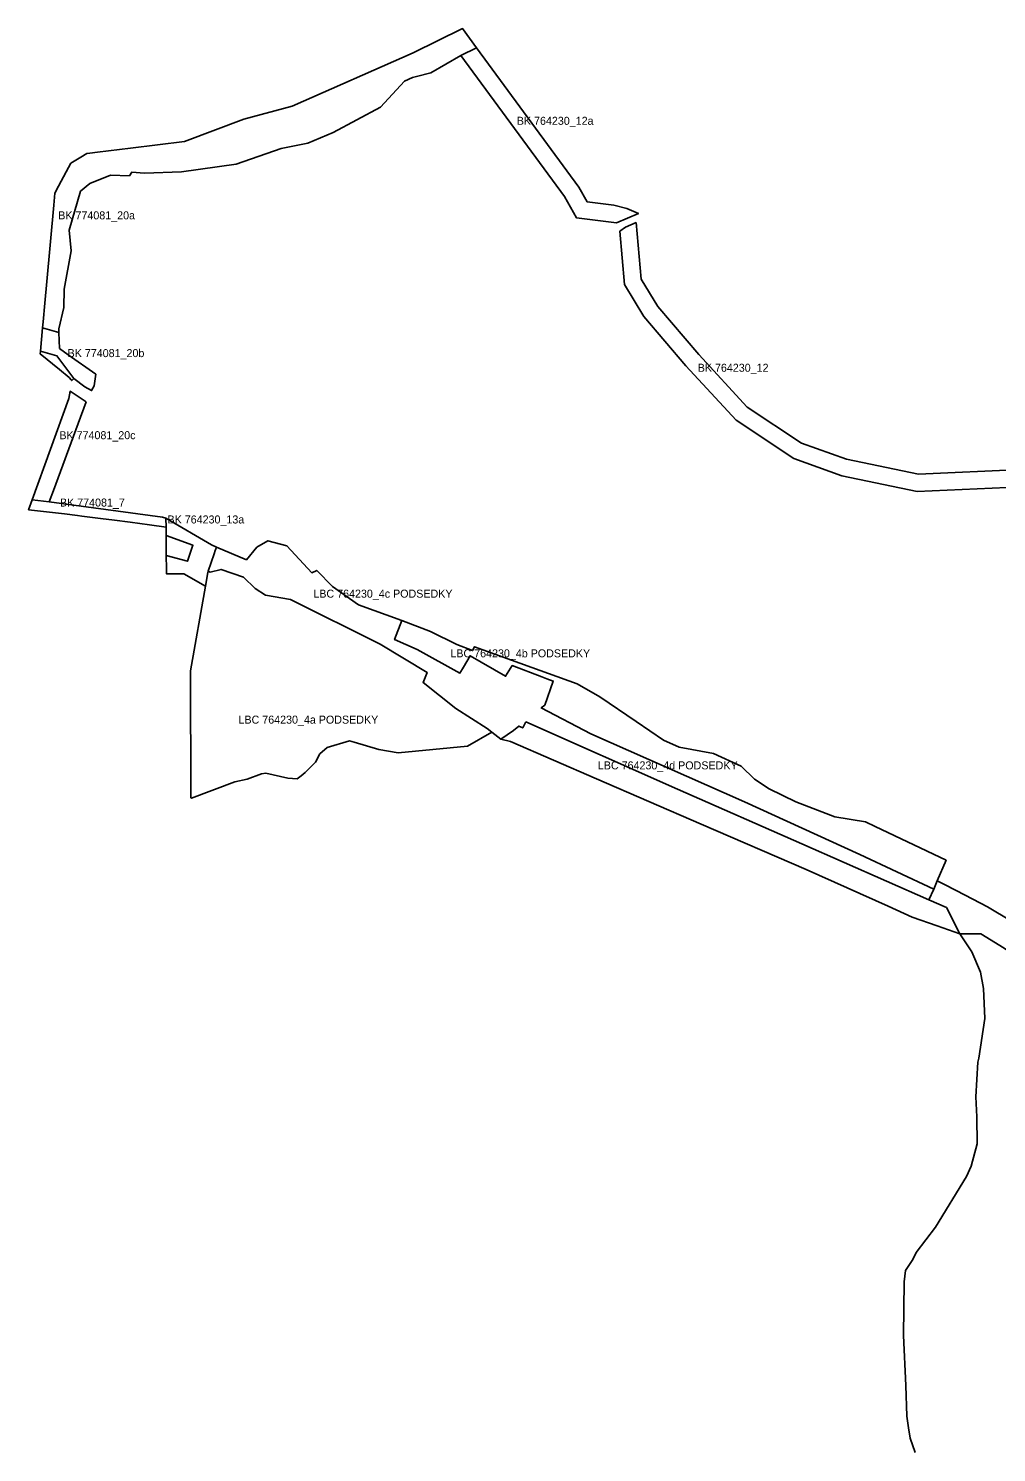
# Model space of a CAD drawing. Extents: x -521616 to -516782, y -1190061 to -1184927.
# Drawn here: x -520810 to -519963, y -1187423 to -1186178 of the extents above; entities that cross this region are included whole.
import ezdxf

# ---------------------------------------------------------------- set-up
doc = ezdxf.new("R2010")
doc.units = 0
for name, color, linetype in [('i_prvek_l_s', 7, 'Continuous'), ('LBC_n', 7, 'Continuous'), ('LBC_s', 7, 'Continuous'), ('LBK_n', 7, 'Continuous'), ('LBK_s', 7, 'Continuous')]:
    doc.layers.add(name, color=color, linetype=linetype)

msp = doc.modelspace()

# ---------------------------------------------------------------- linework, layer by layer
at = {"layer": 'i_prvek_l_s'}
msp.add_lwpolyline([(-520033.7, -1187423.2), (-520038, -1187410.6), (-520039.7, -1187401.5), (-520041.1, -1187391.5), (-520042, -1187364.5), (-520044, -1187320.9), (-520043.3, -1187273.9), (-520042.2, -1187263.9), (-520035.7, -1187254.5), (-520032.9, -1187248.3), (-520016.1, -1187226.1), (-519988.8, -1187181.8), (-519984.8, -1187172.8), (-519979.5, -1187153.1), (-519979.7, -1187129.6), (-519980.7, -1187112.2), (-519979, -1187081.9), (-519978.2, -1187078.4), (-519972.8, -1187043.7), (-519974, -1187017.4), (-519976.6, -1187003), (-519984.1, -1186985.3), (-519994.8, -1186969.5)], dxfattribs=at)
at = {"layer": 'LBC_n'}
msp.add_line((-520652.2, -1186652.3), (-520652.2, -1186652.3), dxfattribs=at)
for points in [[(-520667.4, -1186850.6), (-520667.8, -1186739.5), (-520654.8, -1186665.4), (-520652.7, -1186653.6), (-520652.2, -1186652.3), (-520650.6, -1186653.1), (-520641, -1186650.8), (-520621.4, -1186657.5), (-520611.2, -1186667.5), (-520602.1, -1186673.3), (-520580.3, -1186677), (-520501.9, -1186716.2), (-520460.6, -1186741.1), (-520464.3, -1186749.8), (-520435.6, -1186772.4), (-520408.2, -1186789.8), (-520404, -1186793.2), (-520425.4, -1186805.4), (-520486.2, -1186811.2), (-520503.1, -1186808.4), (-520524.5, -1186802), (-520528.6, -1186800.8), (-520548.3, -1186806.6), (-520554.7, -1186812.2), (-520558.4, -1186819.3), (-520565.6, -1186826.8), (-520567.5, -1186828.5), (-520570.9, -1186831.2), (-520574.5, -1186833.9), (-520582.6, -1186833.3), (-520601.9, -1186829), (-520605.8, -1186829.6), (-520618.2, -1186834.4), (-520629.1, -1186836.6), (-520667, -1186850.8)], [(-520309.6, -1186762.1), (-520278, -1186783.8), (-520253.9, -1186800.1), (-520240.1, -1186806.4), (-520210.1, -1186811.7), (-520185.9, -1186822.9), (-520174.4, -1186834.4), (-520161.4, -1186842.7), (-520138.1, -1186854.2), (-520104.1, -1186867.2), (-520077.1, -1186871.6), (-520068.8, -1186875.6), (-520006.7, -1186905.2), (-520014.4, -1186923.2), (-520017.5, -1186930.4), (-520082.3, -1186900.2), (-520183.2, -1186854.2), (-520317.4, -1186794.6), (-520360.9, -1186771.9), (-520357.9, -1186769.5), (-520350.4, -1186748.5), (-520355.9, -1186746.4), (-520360.4, -1186744.7), (-520386.3, -1186734.9), (-520392.1, -1186744.3), (-520423.1, -1186726.3), (-520429, -1186736.3), (-520432, -1186741.4), (-520469.5, -1186720.7), (-520489.2, -1186712.1), (-520483, -1186695.4), (-520457.7, -1186705), (-520434.7, -1186716.6), (-520421, -1186721.8), (-520419.4, -1186718.5), (-520329.5, -1186750.8)], [(-520374.5, -1186784), (-520241.6, -1186842.9), (-520132.9, -1186890.9), (-520021.9, -1186939.8), (-520006.4, -1186946.6), (-519994.8, -1186969.5), (-520014.6, -1186962.4), (-520036.3, -1186954.9), (-520057.4, -1186945.2), (-520129.2, -1186913.4), (-520221, -1186873.7), (-520312.7, -1186834), (-520387.8, -1186801.4), (-520396.3, -1186799.3), (-520385.2, -1186791.6), (-520380.6, -1186787.9), (-520380.6, -1186787.9), (-520377.1, -1186789.5)]]:
    msp.add_lwpolyline(points, close=True, dxfattribs=at)
at = {"layer": 'LBC_s'}
for p, q in [((-520652.2, -1186652.3), (-520652.2, -1186652.3)), ((-520360.9, -1186771.9), (-520360.9, -1186771.9))]:
    msp.add_line(p, q, dxfattribs=at)
for points in [[(-520374.5, -1186784), (-520377.1, -1186789.5), (-520380.6, -1186787.9), (-520380.6, -1186787.9), (-520385.2, -1186791.6), (-520396.3, -1186799.3), (-520404, -1186793.2), (-520408.2, -1186789.8), (-520435.6, -1186772.4), (-520464.3, -1186749.8), (-520460.6, -1186741.1), (-520501.9, -1186716.2), (-520580.3, -1186677), (-520602.1, -1186673.3), (-520611.2, -1186667.5), (-520621.4, -1186657.5), (-520641, -1186650.8), (-520650.6, -1186653.1), (-520652.2, -1186652.3), (-520652.2, -1186652.3), (-520647.1, -1186637.2), (-520646.1, -1186634.2), (-520645.9, -1186633.8), (-520645.1, -1186631.2), (-520618.9, -1186642.4), (-520609.7, -1186631.4), (-520600.1, -1186625.7), (-520583.6, -1186630.1), (-520561.6, -1186653.7), (-520557.3, -1186651.7), (-520543.5, -1186665.8), (-520520.9, -1186681.9), (-520483, -1186695.4), (-520489.2, -1186712.1), (-520469.5, -1186720.7), (-520432, -1186741.4), (-520429, -1186736.3), (-520423.1, -1186726.3), (-520392.1, -1186744.3), (-520386.3, -1186734.9), (-520360.4, -1186744.7), (-520355.9, -1186746.4), (-520350.4, -1186748.5), (-520357.9, -1186769.5), (-520360.9, -1186771.9)], [(-520360.9, -1186771.9), (-520317.4, -1186794.6), (-520183.2, -1186854.2), (-520082.3, -1186900.2), (-520017.5, -1186930.4), (-520021.9, -1186939.8), (-520132.9, -1186890.9), (-520241.6, -1186842.9)], [(-520241.6, -1186842.9), (-520374.5, -1186784)]]:
    msp.add_lwpolyline(points, dxfattribs=at)
at = {"layer": 'LBK_n'}
for points in [[(-520417.7, -1186194.5), (-520328, -1186316.5), (-520320.7, -1186329.4), (-520297.3, -1186332.2), (-520286, -1186335.2), (-520275.9, -1186339.4), (-520295.1, -1186347.6), (-520330, -1186343.4), (-520340.6, -1186324.7), (-520431.4, -1186201.2)], [(-520759.2, -1186504.2), (-520766.1, -1186523.1), (-520787.7, -1186581.9), (-520791.3, -1186591.7), (-520806.4, -1186589.8), (-520774.1, -1186501.4), (-520773.1, -1186494.9)], [(-520689.2, -1186613.7), (-520703.8, -1186611.8), (-520720.7, -1186609.6), (-520734.4, -1186607.8), (-520746.6, -1186606.3), (-520763, -1186604.1), (-520766.8, -1186603.7), (-520777.9, -1186602.3), (-520809.5, -1186598.6), (-520806.4, -1186589.8), (-520791.3, -1186591.7), (-520692.2, -1186605), (-520689.3, -1186606)], [(-520689.3, -1186606), (-520649.5, -1186629.2), (-520645.1, -1186631.2), (-520645.9, -1186633.8), (-520646.1, -1186634.2), (-520647.1, -1186637.2), (-520652.2, -1186652.3), (-520652.7, -1186653.6), (-520654.8, -1186665.4), (-520673.5, -1186654.6), (-520688.9, -1186654.6), (-520688.9, -1186650.8), (-520688.9, -1186646.6), (-520689, -1186642.4), (-520689, -1186640.8), (-520689, -1186638.6), (-520670.4, -1186643.7), (-520665.7, -1186629.7), (-520689.1, -1186621.2), (-520689.2, -1186617.4), (-520689.2, -1186613.7)]]:
    msp.add_lwpolyline(points, close=True, dxfattribs=at)
for points in [[(-520770, -1186483.8), (-520784.7, -1186463.9), (-520799.1, -1186459.9), (-520797.2, -1186439.6), (-520783, -1186443.6)], [(-520783, -1186443.6), (-520782.5, -1186457.5)], [(-520782.5, -1186457.5), (-520774.7, -1186463.1), (-520750.6, -1186480.1), (-520752.2, -1186490.3), (-520754.3, -1186494.4), (-520760.1, -1186491.2), (-520770, -1186483.8)]]:
    msp.add_lwpolyline(points, dxfattribs=at)
at = {"layer": 'LBK_s'}
for points in [[(-520673, -1186276.5), (-520621.2, -1186257.1), (-520578.8, -1186245.7), (-520473, -1186199), (-520429.8, -1186177.7), (-520417.7, -1186194.5), (-520431.4, -1186201.2), (-520457.5, -1186216.5), (-520470, -1186219.6), (-520473.5, -1186220.4), (-520480.6, -1186223.6), (-520501.5, -1186246.5), (-520543, -1186268.7), (-520565, -1186278), (-520588.5, -1186282.5), (-520627.8, -1186296.3), (-520675.7, -1186303), (-520708, -1186304.1), (-520719, -1186303.2), (-520721.2, -1186306.6), (-520737.8, -1186306), (-520755.9, -1186313.3), (-520763.9, -1186320), (-520774, -1186354.1), (-520772.1, -1186372.2), (-520778.2, -1186405.7), (-520778.6, -1186421.7), (-520783.1, -1186440.4), (-520783, -1186443.6), (-520797.2, -1186439.6), (-520796.7, -1186434.3), (-520795.2, -1186418), (-520793.5, -1186399), (-520787.4, -1186332.3), (-520786.4, -1186321.7), (-520783.2, -1186315.7), (-520776.5, -1186303), (-520772.5, -1186295.5), (-520763.6, -1186290.1), (-520758.4, -1186287), (-520755.8, -1186286.7), (-520749.2, -1186285.9), (-520720.2, -1186282.3)], [(-520277.8, -1186347.4), (-520273.5, -1186396.9), (-520258.9, -1186420.7), (-520223.1, -1186462.9), (-520180.7, -1186508.8), (-520133.2, -1186540.4), (-520093.9, -1186554.5), (-520030.9, -1186567.4), (-519940.8, -1186563.5), (-519927.3, -1186567.4), (-519924.1, -1186584.1), (-519940.2, -1186578.5), (-520032.1, -1186582.5), (-520097.9, -1186568.9), (-520140, -1186553.9), (-520190.5, -1186520.3), (-520234.4, -1186472.8), (-520271.1, -1186429.6), (-520288.2, -1186401.7), (-520292.2, -1186355), (-520287.2, -1186351.5)], [(-520799.1, -1186459.9), (-520784.7, -1186463.9), (-520770, -1186483.8), (-520771.7, -1186485.7), (-520772.2, -1186485.1), (-520774, -1186482.8), (-520782.5, -1186476), (-520799.3, -1186462.3)], [(-520689, -1186631.8), (-520689.1, -1186624.6), (-520689.1, -1186623.1), (-520689.1, -1186621.2), (-520665.7, -1186629.7), (-520670.4, -1186643.7), (-520689, -1186638.6)]]:
    msp.add_lwpolyline(points, close=True, dxfattribs=at)
for points in [[(-520017.5, -1186930.4), (-520014.4, -1186923.2), (-520007.6, -1186926.6), (-519989.9, -1186935.8)], [(-519994.8, -1186969.5), (-520006.4, -1186946.6), (-520021.9, -1186939.8), (-520017.5, -1186930.4)], [(-519989.9, -1186935.8), (-519970.4, -1186945.9), (-519949.4, -1186958.4), (-519930.1, -1186974), (-519913.6, -1186986.4), (-519863.9, -1187030.2), (-519867.2, -1187034.2), (-519876, -1187044.9), (-519880, -1187049.8), (-519882.3, -1187047.6), (-519906.9, -1187024.5), (-519911.6, -1187020.1), (-519928.1, -1187004.6), (-519942.5, -1186991.1), (-519955.8, -1186982.1), (-519976.2, -1186969.6), (-519994.8, -1186969.5)]]:
    msp.add_lwpolyline(points, dxfattribs=at)

# ---------------------------------------------------------------- texts
at = {"layer": 'LBC_n'}
for s, p in [('LBC 764230_4b PODSEDKY', (-520440.4, -1186727.7)), ('LBC 764230_4a PODSEDKY', (-520625.8, -1186785.7)), ('LBC 764230_4d PODSEDKY', (-520311.4, -1186825.7))]:
    msp.add_text(s, height=7, dxfattribs=at).set_placement(p)
at = {"layer": 'LBC_s'}
msp.add_text('LBC 764230_4c PODSEDKY', height=7, dxfattribs=at).set_placement((-520560.3, -1186675.5))
at = {"layer": 'LBK_n'}
for s, p in [('BK 764230_12a', (-520382.3, -1186261.9)), ('BK 774081_20b', (-520775.3, -1186465.1)), ('BK 774081_20c', (-520782.5, -1186536.9)), ('BK 774081_7', (-520782, -1186595.8)), ('BK 764230_13a', (-520687.9, -1186610.6))]:
    msp.add_text(s, height=7, dxfattribs=at).set_placement(p)
at = {"layer": 'LBK_s'}
for s, p in [('BK 774081_20a', (-520783.5, -1186344.6)), ('BK 764230_12', (-520224, -1186477.9))]:
    msp.add_text(s, height=7, dxfattribs=at).set_placement(p)

doc.saveas('drawing.dxf')
